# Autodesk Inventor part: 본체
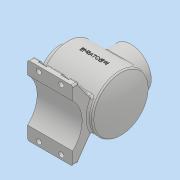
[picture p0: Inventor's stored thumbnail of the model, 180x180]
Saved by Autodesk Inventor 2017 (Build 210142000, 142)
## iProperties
Part Number: 본체
Material: 일반
Document SubType Name: Modeling
Designer: MRC
Density: 1 g/cm^3
Appearance: 기본값
Author: MRC
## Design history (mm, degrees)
sketch "스케치1"
  geometry: L1 (0, 36)-(12, 36); L2 (12, 36)-(12, 50); L3 (12, 50)-(108.336, 50); L4 (0, 0)-(120, 0); L5 (0, 27)-(19, 27); L6 (19, 27)-(19, 43); L7 (19, 43)-(103.887, 43); L8 (0, 36)-(0, 27); A1 r 113 centre (7, 0) between (120, 0) and (108.336, 50); A2 r 106 centre (7, 0) between (113, 0) and (103.887, 43)
  constraints: 16 end point, 4 point on circle, 3 horizontal, 3 perpendicular, 3 point on line, 2 centre point, 1 concentric, 1 parallel, 1 vertical, 1 vertical alignment
  dimensions: "d0" = 36 distance of L4.start L1.start; "d1" = 50 distance from line of L4.start L3; "d2" = 12 distance of L1.start L1.end; "d4" = 113 radius of A1; "d5" = 120 distance of L4.end L4.start; "d6" = 19 distance of L5.start L5.end; "d7" = 27 distance from line of A1.centre L5; "d8" = 86 diameter of L7 L4; "d11" = 7 distance of L4.end A2.start
revolve "회전1" sketch "스케치1" stored, may be unused: angle "d12" = 90 deg
node "작업 평면1"
sketch "스케치2"
  geometry: C1 r 36 at (-62, 0); 1 further point
  constraints: 1 centre point, 1 horizontal alignment
  dimensions: "d14" = 72 diameter of C1; "d15" = 62 distance of C1.centre point (0, 0)
extrude "돌출1" join sketch "스케치2" stored distance "d16" = 0; taper "d17" = 0 deg
sketch "스케치3"
  geometry: C1 r 27 at (0, 0); C2 r 36 at (0, 0) reference; 1 further point
  constraints: 1 centre point, 1 concentric
  dimensions: "d18" = 54 diameter of C1
extrude "돌출2" cut sketch "스케치3" distance "d19" = 45.75; taper "d20" = 0 deg
node "작업 평면3"
sketch "스케치5"
  geometry: L1 (-42.278, -26.694)-(-67, -62); L2 (-67, -62)-(-77, -62); L3 (-77, 62)-(-67, 62); L4 (-67, 62)-(-42.278, 26.694); L5 (-77, -62)-(-77, -38.5); L6 (-77, 38.5)-(-77, 62); A1 r 50 centre (0, 0) between (-42.278, -26.694) and (-42.278, 26.694) reference; A2 r 52.096 centre (-112.096, 0) between (-77, -38.5) and (-77, 38.5); 1 further point
  constraints: 12 end point, 4 perpendicular, 4 point on circle, 1 centre point, 1 horizontal, 1 horizontal alignment, 1 vertical alignment
  dimensions: "d25" = 124 distance of L2.end L3.start; "d26" = 10 distance of L1.end L2.end; "d28" = 10 distance of L3.start L3.end; "d29" = 55 deg angle of L3 L4; "d30" = 55 deg angle of L2 L1; "d35" = 77 distance from line of L6 point (0, 0); "d36" = 62 vertical distance of L3.start point (0, 0); "d37" = 17 distance edge to line of A2 L6; "d38" = 77 distance of L6.start L5.end
extrude "돌출3" join sketch "스케치5" distance "d31" = 80; taper "d32" = 0 deg
node "작업 평면4"
sketch "스케치9"
  geometry: L1 (100, 62)-(100, 38.5) reference; L2 (20, 62)-(100, 62) reference; C1 r 4.5 at (80, 54); C2 r 4.5 at (80, -54); C3 r 4.5 at (40, -54); C4 r 4.5 at (40, 54); 1 further point
  constraints: 4 centre point, 2 horizontal alignment, 2 vertical alignment
  dimensions: "d46" = 9 diameter of C1; "d47" = 20 distance from line of L1 C1.centre; "d48" = 9 diameter of C2; "d49" = 9 diameter of C3; "d50" = 9 diameter of C4; "d51" = 40 distance of C4.centre C1.centre; "d52" = 108 distance of C1.centre C2.centre; "d53" = 8 distance from line of L2 C1.centre
extrude "돌출4" cut sketch "스케치9" distance "d54" = 6; taper "d55" = 0 deg
node "작업 평면5"
sketch "스케치11"
  geometry: L1 (87, 54)-(87, 62); L2 (20, 62)-(100, 62) reference; L3 (73, 54)-(73, 62); L4 (12, 50)-(108.336, 50) reference; L5 (47, 54)-(47, 62); L6 (33, 54)-(33, 62); L7 (87, -54)-(87, -62); L8 (20, -62)-(100, -62) reference; L9 (73, -54)-(73, -62); L10 (47, -54)-(47, -62); L11 (33, -54)-(33, -62); C1 r 4.5 at (80, 54) reference; C2 r 4.5 at (40, 54) reference; C3 r 4.5 at (40, -54) reference; C4 r 4.5 at (80, -54) reference; A1 r 7 centre (80, 54) between (73, 54) and (87, 54); A2 r 7 centre (40, 54) between (33, 54) and (47, 54); A3 r 7 centre (80, -54) between (87, -54) and (73, -54); A4 r 7 centre (40, -54) between (47, -54) and (33, -54); 1 further point
  constraints: 16 end point, 12 point on line, 8 point on circle, 6 tangent, 4 centre point, 3 concentric, 3 parallel, 2 perpendicular, 1 coincident, 1 vertical
  dimensions: "d61" = 14 diameter of A3; "d62" = 14 diameter of A4; "d63" = 14 diameter of A2; "d64" = 14 diameter of A1
extrude "돌출5" cut sketch "스케치11" distance "d65" = 19.25; taper "d66" = 0 deg
sketch "스케치12"
  geometry: 2 further points
  constraints: 1 vertical alignment
  dimensions: "d67" = 32.5 distance of point (0, 32.5) point (0, 0)
hole "구멍1" sketch "스케치12" at (0, 32.5) diameter "d68" = 3.242; stored, may be unused: countersink angle "d72" = 90 deg, drill point angle "d74" = 118 deg; dims "d69" = 8, "d70" = 4, "d71" = 2, "d73" = 10
sketch "스케치13"
  geometry: C1 r 27 at (0, 0) reference; 2 further points
  constraints: 1 vertical alignment
  dimensions: "d78" = 32.5 distance of C1.centre point (0, 32.5)
hole "구멍2" sketch "스케치13" at (0, 32.5) diameter "d79" = 3.242; stored, may be unused: countersink angle "d83" = 90 deg, drill point angle "d85" = 118 deg; dims "d80" = 8, "d81" = 4, "d82" = 2, "d84" = 10
node "작업 평면6"
sketch "스케치14"
  geometry: 2 further points
  constraints: 1 horizontal alignment, 1 other
  dimensions: "d90" = 62 distance of point (0, 0) point (62, 0)
feature "엠보싱1" sketch "스케치14" dims "d91" = 0.5, "d92" = 0
chamfer "모따기1" distance "d93" = 1; stored, may be unused: second distance "d94" = 2, angle "d95" = 45 deg
fillet "모깎기1" dims "d96" = 3
fillet "모깎기2" dims "d97" = 3
fillet "모깎기3" dims "d98" = 3
fillet "모깎기4" dims "d99" = 3
fillet "모깎기5" dims "d100" = 3
node "솔리드1"
pattern_circular "원형 패턴1" dims angle "d76" = 360 deg
pattern_circular "원형 패턴2" dims angle "d87" = 360 deg
other parameters: "d13" = 65, "d27" = 77, "d45" = -77, "d60" = -71, "d89" = 51.25
